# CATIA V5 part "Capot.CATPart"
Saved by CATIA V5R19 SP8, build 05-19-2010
Part number: Capot
Bounding box of the stored display mesh (mm): x -4 to 0, y -57 to 57, z -56.805 to 56.805
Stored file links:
  G:\EU_thinkMotion\CFAO_2010\SIL_groupe2\SIL_groupe2\msauret\Brevet_Sauret_parametre\Capot.CATPart
  F:\Brevet_Sauret paramétré\Product3.CATProduct
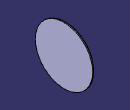
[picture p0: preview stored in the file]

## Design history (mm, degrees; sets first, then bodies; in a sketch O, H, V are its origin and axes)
Set1
  Plane1: linked copy from another document
Body1 (main body)
  Sketch1 on Plane1, origin (0, 0, 0), H (0, 1, 0), V (0, 0, 1)
    circle A1 centre (0, 0) radius 57
  Pad1: profile Sketch1, direction (-1, 0, 0), length 2
  Sketch2 on end face of Pad1, origin (-2, 0, 0), H (0, -1, 0), V (0, 0, 1)
    circle A1 centre (0, 0) radius 55
    point P1 (0, 0)
    coincidence: P1 V
  Pad2: profile Sketch2, direction (-1, 0, 0), length 2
